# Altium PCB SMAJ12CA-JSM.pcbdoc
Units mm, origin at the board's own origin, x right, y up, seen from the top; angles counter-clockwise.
Board outline 19.1 x 15.55 mm, 2 copper layers (Top Layer, Bottom Layer), stack 0 mm thick; 1 components, 0 nets, 2 pads, 0 vias.
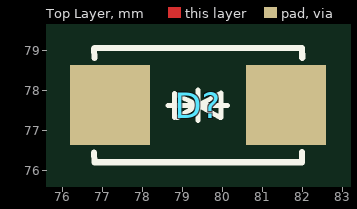
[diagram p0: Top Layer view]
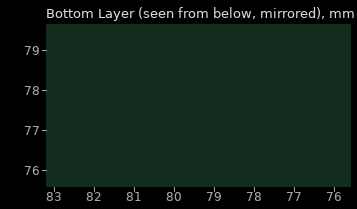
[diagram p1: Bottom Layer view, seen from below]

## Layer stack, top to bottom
Top Layer: signal copper (thickness not stored)
Bottom Layer: signal copper (thickness not stored)

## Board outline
88.95,69.85 69.85,69.85 69.85,85.402 88.95,85.402

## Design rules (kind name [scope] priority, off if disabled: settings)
PasteMaskExpansion "Paste Mask Expansion" [All] p1: expansion=0
SolderMaskExpansion "Solder Mask Expansion" [IsVia] p1: expansion=-25.4 istentingtop=TRUE
SolderMaskExpansion "Solder Mask Expansion" [All] p2: expansion=0.051 istentingtop=FALSE

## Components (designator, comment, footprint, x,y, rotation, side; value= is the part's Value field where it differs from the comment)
D? "SMAJ12CA-JSM" SMA_L4.3-W2.6-LS5.1-BI 79.4,77.626 r0 top

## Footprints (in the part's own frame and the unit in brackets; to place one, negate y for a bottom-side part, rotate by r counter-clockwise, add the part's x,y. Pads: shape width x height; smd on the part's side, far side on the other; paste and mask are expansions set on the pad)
SMA_L4.3-W2.6-LS5.1-BI [mm]
  rect 2x2 smd: 1(-2.2,0) 2(2.2,0)
  silkscreen extent -2.6,-1.43 2.6,1.43

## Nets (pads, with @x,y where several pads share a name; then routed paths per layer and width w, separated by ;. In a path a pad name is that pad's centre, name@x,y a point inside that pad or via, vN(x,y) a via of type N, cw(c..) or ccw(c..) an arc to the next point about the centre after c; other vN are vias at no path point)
pads on no net: D?.1 D?.2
